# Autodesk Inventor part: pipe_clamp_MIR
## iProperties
Shininess: 64.0
Length Units: 11272
Angle Units: 11279
Time Units: 11290
Mass Units: 11286
Length Display Precision: 3
Angle Display Precision: 2
Compacted: True
Part Number: pipe_clamp_MIR
Document SubType Name: Modeling
Created: 2004-08
Designer: John Blackburn
Material: Default
Manufacturer: Standard
Standards Organization: Custom
Density: 0.0
Volumn: 0.0
Area: 0.0
PropertySet Name: Model Information
Control State: 0
Master: False
Checked Out: False
Author: John Blackburn
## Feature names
1. Derived Body1 [Tagging]
